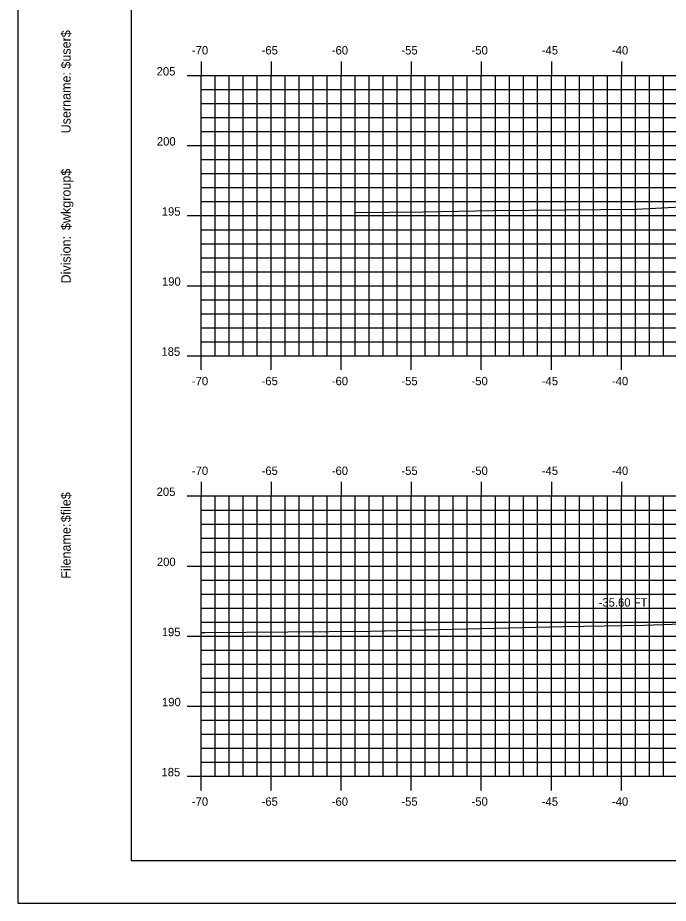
# Model space of a CAD drawing. Extents: x 1138985 to 1139155, y 608981 to 609091.
# Drawn here: x 1138984.9 to 1139031.3, y 608981.3 to 609044.5 of the extents above; entities that cross this region are included whole.
import ezdxf

# ---------------------------------------------------------------- set-up
doc = ezdxf.new("R2010")
doc.units = 0
for name, color, linetype in [('BORDER', 7, 'Continuous'), ('D_Text_Standard', 7, 'Continuous'), ('H_V ANNOTATION', 7, 'Continuous'), ('MAJOR', 7, 'Continuous'), ('MINOR', 7, 'Continuous'), ('PLOT BOUNDARY', 7, 'Continuous'), ('S_Roadway_Centerline', 7, 'Continuous')]:
    doc.layers.add(name, color=color, linetype=linetype)

msp = doc.modelspace()

# ---------------------------------------------------------------- linework, layer by layer
at = {"layer": 'BORDER'}
msp.add_lwpolyline([(1138992.949, 608984.335), (1139152.949, 608984.335), (1139152.949, 609089.335), (1138992.949, 609089.335)], close=True, dxfattribs=at)
at = {"layer": 'MAJOR'}
for p, q in [((1138997.949, 609041.337), (1138997.949, 609040.335)), ((1139002.949, 609041.337), (1139002.949, 609040.335)), ((1139007.949, 609041.337), (1139007.949, 609040.335)), ((1139012.949, 609041.337), (1139012.949, 609040.335)), ((1139017.949, 609041.337), (1139017.949, 609040.335)), ((1139022.949, 609041.337), (1139022.949, 609040.335)), ((1139027.949, 609041.337), (1139027.949, 609040.335)), ((1138996.947, 609040.335), (1138997.949, 609040.335)), ((1138997.949, 609040.335), (1139137.949, 609040.335)), ((1138997.949, 609020.335), (1138997.949, 609040.335)), ((1138997.949, 609020.335), (1138997.949, 609040.335)), ((1138997.949, 609040.335), (1139137.949, 609040.335)), ((1139002.949, 609020.335), (1139002.949, 609040.335)), ((1139007.949, 609020.335), (1139007.949, 609040.335)), ((1139012.949, 609020.335), (1139012.949, 609040.335)), ((1139017.949, 609020.335), (1139017.949, 609040.335)), ((1139022.949, 609020.335), (1139022.949, 609040.335)), ((1139027.949, 609020.335), (1139027.949, 609040.335)), ((1138996.947, 609035.335), (1138997.949, 609035.335)), ((1138997.949, 609035.335), (1139137.949, 609035.335)), ((1138996.947, 609030.335), (1138997.949, 609030.335)), ((1138997.949, 609030.335), (1139137.949, 609030.335)), ((1138996.947, 609025.335), (1138997.949, 609025.335)), ((1138997.949, 609025.335), (1139137.949, 609025.335)), ((1138996.947, 609020.335), (1138997.949, 609020.335)), ((1138997.949, 609020.335), (1139137.949, 609020.335)), ((1138997.949, 609020.335), (1139137.949, 609020.335)), ((1138997.949, 609019.333), (1138997.949, 609020.335)), ((1139002.949, 609019.333), (1139002.949, 609020.335)), ((1139007.949, 609019.333), (1139007.949, 609020.335)), ((1139012.949, 609019.333), (1139012.949, 609020.335)), ((1139017.949, 609019.333), (1139017.949, 609020.335)), ((1139022.949, 609019.333), (1139022.949, 609020.335)), ((1139027.949, 609019.333), (1139027.949, 609020.335)), ((1138997.949, 609011.337), (1138997.949, 609010.335)), ((1139002.949, 609011.337), (1139002.949, 609010.335)), ((1139007.949, 609011.337), (1139007.949, 609010.335)), ((1139012.949, 609011.337), (1139012.949, 609010.335)), ((1139017.949, 609011.337), (1139017.949, 609010.335)), ((1139022.949, 609011.337), (1139022.949, 609010.335)), ((1139027.949, 609011.337), (1139027.949, 609010.335)), ((1138996.947, 609010.335), (1138997.949, 609010.335)), ((1138997.949, 609010.335), (1139137.949, 609010.335)), ((1138997.949, 608990.335), (1138997.949, 609010.335)), ((1138997.949, 608990.335), (1138997.949, 609010.335)), ((1138997.949, 609010.335), (1139137.949, 609010.335)), ((1139002.949, 608990.335), (1139002.949, 609010.335)), ((1139007.949, 608990.335), (1139007.949, 609010.335)), ((1139012.949, 608990.335), (1139012.949, 609010.335)), ((1139017.949, 608990.335), (1139017.949, 609010.335)), ((1139022.949, 608990.335), (1139022.949, 609010.335)), ((1139027.949, 608990.335), (1139027.949, 609010.335)), ((1138996.947, 609005.335), (1138997.949, 609005.335)), ((1138997.949, 609005.335), (1139137.949, 609005.335)), ((1138996.947, 609000.335), (1138997.949, 609000.335)), ((1138997.949, 609000.335), (1139137.949, 609000.335)), ((1138996.947, 608995.335), (1138997.949, 608995.335)), ((1138997.949, 608995.335), (1139137.949, 608995.335)), ((1138996.947, 608990.335), (1138997.949, 608990.335)), ((1138997.949, 608990.335), (1139137.949, 608990.335)), ((1138997.949, 608990.335), (1139137.949, 608990.335)), ((1138997.949, 608989.333), (1138997.949, 608990.335)), ((1139002.949, 608989.333), (1139002.949, 608990.335)), ((1139007.949, 608989.333), (1139007.949, 608990.335)), ((1139012.949, 608989.333), (1139012.949, 608990.335)), ((1139017.949, 608989.333), (1139017.949, 608990.335)), ((1139022.949, 608989.333), (1139022.949, 608990.335)), ((1139027.949, 608989.333), (1139027.949, 608990.335))]:
    msp.add_line(p, q, dxfattribs=at)
at = {"layer": 'MINOR'}
for p, q in [((1138998.949, 609020.335), (1138998.949, 609040.335)), ((1138999.949, 609020.335), (1138999.949, 609040.335)), ((1139000.949, 609020.335), (1139000.949, 609040.335)), ((1139001.949, 609020.335), (1139001.949, 609040.335)), ((1139003.949, 609020.335), (1139003.949, 609040.335)), ((1139004.949, 609020.335), (1139004.949, 609040.335)), ((1139005.949, 609020.335), (1139005.949, 609040.335)), ((1139006.949, 609020.335), (1139006.949, 609040.335)), ((1139008.949, 609020.335), (1139008.949, 609040.335)), ((1139009.949, 609020.335), (1139009.949, 609040.335)), ((1139010.949, 609020.335), (1139010.949, 609040.335)), ((1139011.949, 609020.335), (1139011.949, 609040.335)), ((1139013.949, 609020.335), (1139013.949, 609040.335)), ((1139014.949, 609020.335), (1139014.949, 609040.335)), ((1139015.949, 609020.335), (1139015.949, 609040.335)), ((1139016.949, 609020.335), (1139016.949, 609040.335)), ((1139018.949, 609020.335), (1139018.949, 609040.335)), ((1139019.949, 609020.335), (1139019.949, 609040.335)), ((1139020.949, 609020.335), (1139020.949, 609040.335)), ((1139021.949, 609020.335), (1139021.949, 609040.335)), ((1139023.949, 609020.335), (1139023.949, 609040.335)), ((1139024.949, 609020.335), (1139024.949, 609040.335)), ((1139025.949, 609020.335), (1139025.949, 609040.335)), ((1139026.949, 609020.335), (1139026.949, 609040.335)), ((1139028.949, 609020.335), (1139028.949, 609040.335)), ((1139029.949, 609020.335), (1139029.949, 609040.335)), ((1139030.949, 609020.335), (1139030.949, 609040.335)), ((1138997.949, 609039.335), (1139137.949, 609039.335)), ((1138997.949, 609039.335), (1138998.951, 609039.335)), ((1138997.949, 609038.335), (1139137.949, 609038.335)), ((1138997.949, 609038.335), (1138998.951, 609038.335)), ((1138997.949, 609037.335), (1139137.949, 609037.335)), ((1138997.949, 609037.335), (1138998.951, 609037.335)), ((1138997.949, 609036.335), (1139137.949, 609036.335)), ((1138997.949, 609036.335), (1138998.951, 609036.335)), ((1138997.949, 609034.335), (1139137.949, 609034.335)), ((1138997.949, 609034.335), (1138998.951, 609034.335)), ((1138997.949, 609033.335), (1139137.949, 609033.335)), ((1138997.949, 609033.335), (1138998.951, 609033.335)), ((1138997.949, 609032.335), (1139137.949, 609032.335)), ((1138997.949, 609032.335), (1138998.951, 609032.335)), ((1138997.949, 609031.335), (1139137.949, 609031.335)), ((1138997.949, 609031.335), (1138998.951, 609031.335)), ((1138997.949, 609029.335), (1139137.949, 609029.335)), ((1138997.949, 609029.335), (1138998.951, 609029.335)), ((1138997.949, 609028.335), (1139137.949, 609028.335)), ((1138997.949, 609028.335), (1138998.951, 609028.335)), ((1138997.949, 609027.335), (1139137.949, 609027.335)), ((1138997.949, 609027.335), (1138998.951, 609027.335)), ((1138997.949, 609026.335), (1139137.949, 609026.335)), ((1138997.949, 609026.335), (1138998.951, 609026.335)), ((1138997.949, 609024.335), (1139137.949, 609024.335)), ((1138997.949, 609024.335), (1138998.951, 609024.335)), ((1138997.949, 609023.335), (1139137.949, 609023.335)), ((1138997.949, 609023.335), (1138998.951, 609023.335)), ((1138997.949, 609022.335), (1139137.949, 609022.335)), ((1138997.949, 609022.335), (1138998.951, 609022.335)), ((1138997.949, 609021.335), (1139137.949, 609021.335)), ((1138997.949, 609021.335), (1138998.951, 609021.335)), ((1138998.949, 608990.335), (1138998.949, 609010.335)), ((1138999.949, 608990.335), (1138999.949, 609010.335)), ((1139000.949, 608990.335), (1139000.949, 609010.335)), ((1139001.949, 608990.335), (1139001.949, 609010.335)), ((1139003.949, 608990.335), (1139003.949, 609010.335)), ((1139004.949, 608990.335), (1139004.949, 609010.335)), ((1139005.949, 608990.335), (1139005.949, 609010.335)), ((1139006.949, 608990.335), (1139006.949, 609010.335)), ((1139008.949, 608990.335), (1139008.949, 609010.335)), ((1139009.949, 608990.335), (1139009.949, 609010.335)), ((1139010.949, 608990.335), (1139010.949, 609010.335)), ((1139011.949, 608990.335), (1139011.949, 609010.335)), ((1139013.949, 608990.335), (1139013.949, 609010.335)), ((1139014.949, 608990.335), (1139014.949, 609010.335)), ((1139015.949, 608990.335), (1139015.949, 609010.335)), ((1139016.949, 608990.335), (1139016.949, 609010.335)), ((1139018.949, 608990.335), (1139018.949, 609010.335)), ((1139019.949, 608990.335), (1139019.949, 609010.335)), ((1139020.949, 608990.335), (1139020.949, 609010.335)), ((1139021.949, 608990.335), (1139021.949, 609010.335)), ((1139023.949, 608990.335), (1139023.949, 609010.335)), ((1139024.949, 608990.335), (1139024.949, 609010.335)), ((1139025.949, 608990.335), (1139025.949, 609010.335)), ((1139026.949, 608990.335), (1139026.949, 609010.335)), ((1139028.949, 608990.335), (1139028.949, 609010.335)), ((1139029.949, 608990.335), (1139029.949, 609010.335)), ((1139030.949, 608990.335), (1139030.949, 609010.335)), ((1138997.949, 609009.335), (1139137.949, 609009.335)), ((1138997.949, 609009.335), (1138998.951, 609009.335)), ((1138997.949, 609008.335), (1139137.949, 609008.335)), ((1138997.949, 609008.335), (1138998.951, 609008.335)), ((1138997.949, 609007.335), (1139137.949, 609007.335)), ((1138997.949, 609007.335), (1138998.951, 609007.335)), ((1138997.949, 609006.335), (1139137.949, 609006.335)), ((1138997.949, 609006.335), (1138998.951, 609006.335)), ((1138997.949, 609004.335), (1139137.949, 609004.335)), ((1138997.949, 609004.335), (1138998.951, 609004.335)), ((1138997.949, 609003.335), (1139137.949, 609003.335)), ((1138997.949, 609003.335), (1138998.951, 609003.335)), ((1138997.949, 609002.335), (1139137.949, 609002.335)), ((1138997.949, 609002.335), (1138998.951, 609002.335)), ((1138997.949, 609001.335), (1139137.949, 609001.335)), ((1138997.949, 609001.335), (1138998.951, 609001.335)), ((1138997.949, 608999.335), (1139137.949, 608999.335)), ((1138997.949, 608999.335), (1138998.951, 608999.335)), ((1138997.949, 608998.335), (1139137.949, 608998.335)), ((1138997.949, 608998.335), (1138998.951, 608998.335)), ((1138997.949, 608997.335), (1139137.949, 608997.335)), ((1138997.949, 608997.335), (1138998.951, 608997.335)), ((1138997.949, 608996.335), (1139137.949, 608996.335)), ((1138997.949, 608996.335), (1138998.951, 608996.335)), ((1138997.949, 608994.335), (1139137.949, 608994.335)), ((1138997.949, 608994.335), (1138998.951, 608994.335)), ((1138997.949, 608993.335), (1139137.949, 608993.335)), ((1138997.949, 608993.335), (1138998.951, 608993.335)), ((1138997.949, 608992.335), (1139137.949, 608992.335)), ((1138997.949, 608992.335), (1138998.951, 608992.335)), ((1138997.949, 608991.335), (1139137.949, 608991.335)), ((1138997.949, 608991.335), (1138998.951, 608991.335))]:
    msp.add_line(p, q, dxfattribs=at)
at = {"layer": 'PLOT BOUNDARY'}
msp.add_lwpolyline([(1138984.856, 608981.276), (1139154.856, 608981.276), (1139154.856, 609091.276), (1138984.856, 609091.276)], close=True, dxfattribs=at)
at = {"layer": 'S_Roadway_Centerline'}
for points in [[(1139008.964, 609030.568), (1139013.802, 609030.617), (1139018.789, 609030.701), (1139029.012, 609030.802), (1139036.333, 609031.172), (1139038.36, 609031.267), (1139051.717, 609031.692), (1139055.192, 609031.796), (1139055.286, 609031.839), (1139057.512, 609031.91), (1139058.507, 609031.916), (1139058.609, 609031.937), (1139066.993, 609031.972), (1139069.75, 609032.014), (1139078.062, 609031.769), (1139080.017, 609031.708), (1139082.039, 609031.345), (1139084.628, 609031.083), (1139088.442, 609029.697)], [(1138997.949, 609000.594), (1138998.212, 609000.594), (1139010.067, 609000.697), (1139023.809, 609001.027), (1139029.59, 609001.116), (1139032.226, 609001.203), (1139041.14, 609001.588), (1139053.415, 609002.2), (1139055.024, 609002.334), (1139055.142, 609002.388), (1139056.663, 609002.437), (1139058.25, 609002.447), (1139058.412, 609002.48), (1139064.476, 609002.505), (1139069.549, 609002.583), (1139076.026, 609002.392), (1139079.831, 609002.273), (1139083.768, 609001.567), (1139084.499, 609001.493), (1139085.575, 609001.102), (1139092.172, 608999.144)]]:
    msp.add_lwpolyline(points, dxfattribs=at)

# ---------------------------------------------------------------- texts
at = {"layer": 'BORDER'}
for s, p in [('$user$', (1138988.634, 609040.827)), ('Username:', (1138988.634, 609036.203)), ('$wkgroup$', (1138988.634, 609029.305)), ('Division:', (1138988.634, 609025.501)), ('$file$', (1138988.634, 609008.461)), ('Filename:', (1138988.634, 609004.433))]:
    msp.add_text(s, height=0.6696, rotation=90, dxfattribs=at).set_placement(p)
at = {"layer": 'D_Text_Standard'}
msp.add_text('-35.60 FT', height=0.6, dxfattribs=at).set_placement((1139026.326, 609002.442))
at = {"layer": 'H_V ANNOTATION'}
for s, p in [('-70', (1138997.29, 609041.835)), ('-65', (1139002.266, 609041.835)), ('-60', (1139007.274, 609041.835)), ('-55', (1139012.245, 609041.835)), ('-50', (1139017.253, 609041.835)), ('-45', (1139022.266, 609041.835)), ('-40', (1139027.274, 609041.835)), ('205', (1138994.773, 609040.335)), ('200', (1138994.789, 609035.335)), ('195', (1138995.138, 609030.335)), ('190', (1138995.154, 609025.335)), ('185', (1138995.116, 609020.335)), ('-70', (1138997.29, 609018.235)), ('-65', (1139002.266, 609018.235)), ('-60', (1139007.274, 609018.235)), ('-55', (1139012.245, 609018.235)), ('-50', (1139017.253, 609018.235)), ('-45', (1139022.266, 609018.235)), ('-40', (1139027.274, 609018.235)), ('-70', (1138997.29, 609011.835)), ('-65', (1139002.266, 609011.835)), ('-60', (1139007.274, 609011.835)), ('-55', (1139012.245, 609011.835)), ('-50', (1139017.253, 609011.835)), ('-45', (1139022.266, 609011.835)), ('-40', (1139027.274, 609011.835)), ('205', (1138994.773, 609010.335)), ('200', (1138994.789, 609005.335)), ('195', (1138995.138, 609000.335)), ('190', (1138995.154, 608995.335)), ('185', (1138995.116, 608990.335)), ('-70', (1138997.29, 608988.235)), ('-65', (1139002.266, 608988.235)), ('-60', (1139007.274, 608988.235)), ('-55', (1139012.245, 608988.235)), ('-50', (1139017.253, 608988.235)), ('-45', (1139022.266, 608988.235)), ('-40', (1139027.274, 608988.235))]:
    msp.add_text(s, height=0.6, dxfattribs=at).set_placement(p)
at = {"layer": 'MAJOR'}
for p in [(1138997.944, 609020.335), (1138997.944, 608990.335)]:
    msp.add_text('-', height=0.006, dxfattribs=at).set_placement(p)

doc.saveas('drawing.dxf')
